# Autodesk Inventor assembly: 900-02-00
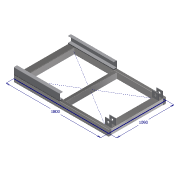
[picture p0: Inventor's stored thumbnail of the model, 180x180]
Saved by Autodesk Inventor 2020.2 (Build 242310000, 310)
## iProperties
Created: 2015-10
Part Number: 900-02-00
Document SubType Name: Konstrukcja spawana
Designer: F.Stasiak
Weld Material: Stal, miękka, spawana
Mass: 81980 g
Surface Area: 59876.8 cm^2
Volume: 13260.1 cm^3
Density: 6.18248 g/cm^3
Catalog Web Link: www.expertbooks.pl
Manager: www.cadconsulting.pl
Company: Fabian Stasiak CAD Consulting
_SolveAssemblyDoc: Frame Generator Solve Assembly
_Version: 15.0.0
Author: F.Stasiak
Subject: Zbiór ćwiczeń. Autodesk Inventor 2020. Kurs Professional
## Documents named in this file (6)
- C:\2020_Kurs_Professional\R3 Dynamika\Komponenty_dyn\900-02-00.iam
- C:\2020_Kurs_Professional\R3 Dynamika\Komponenty_dyn\900-01-00_Szkielet.ipt
- C:\2020_Kurs_Professional\R3 Dynamika\900-01\Frame\Frame_900_01_00.iam
- C:\2020_Kurs_Professional\R3 Dynamika\Komponenty_dyn\900-01-06.ipt
- C:\2020_Kurs_Professional\R3 Dynamika\Komponenty_dyn\900-01-07.ipt
- C:\2020_Kurs_Professional\R3 Dynamika\Komponenty_dyn\EN 10058 - 900-01-08.ipt
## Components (10 placed, 5 different names)
1. 900-01-00_Szkielet:1
2. Frame_900_01_00:1 [sub-assembly] — Zestawiający:1, Równoległy:1, Równoległy:2, Zestawiający:2, Równoległy:3, Równoległy:4, Zestawiający:3, Równoległy:5, Zestawiający:4, Równoległy:7, Równoległy:8, Zestawiający:5, Zestawiający:7, Równoległy:6, Zestawiający:9, Zestawiający:10, Równoległy:13, Równoległy:14, Zestawiający:13
3. 900-01-06:1 — Zestawiający:1, Równoległy:1, Równoległy:2
4. 900-01-06:2 — Zestawiający:2, Równoległy:3, Równoległy:4, Równoległy:11, Równoległy:12
5. 900-01-07:1 — Zestawiający:3, Równoległy:5, Równoległy:6, Równoległy:9, Zestawiający:6
6. 900-01-07:2 — Zestawiający:4, Równoległy:7, Równoległy:8, Równoległy:10, Zestawiający:8
7. 900-01-07:3 — Zestawiający:5, Równoległy:9, Zestawiający:6
8. 900-01-07:4 — Zestawiający:7, Równoległy:10, Zestawiający:8
9. EN 10058 - 900-01-08:1 — Zestawiający:9, Równoległy:11, Równoległy:12
10. EN 10058 - 900-01-08:2 — Zestawiający:10, Równoległy:13, Równoległy:14
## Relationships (25: Flush 14, Mate 11)
- Zestawiający:1 [Mate]: Frame_900_01_00:1 ↔ 900-01-06:1
- Równoległy:1 [Flush]: Frame_900_01_00:1 ↔ 900-01-06:1
- Równoległy:2 [Flush]: Frame_900_01_00:1 ↔ 900-01-06:1
- Zestawiający:2 [Mate]: Frame_900_01_00:1 ↔ 900-01-06:2
- Równoległy:3 [Flush]: Frame_900_01_00:1 ↔ 900-01-06:2
- Równoległy:4 [Flush]: Frame_900_01_00:1 ↔ 900-01-06:2
- Zestawiający:3 [Mate]: Frame_900_01_00:1 ↔ 900-01-07:1
- Równoległy:5 [Flush]: Frame_900_01_00:1 ↔ 900-01-07:1
- Równoległy:6 [Flush]: Frame_900_01_00:1 ↔ 900-01-07:1
- Zestawiający:4 [Mate]: Frame_900_01_00:1 ↔ 900-01-07:2
- Równoległy:7 [Flush]: Frame_900_01_00:1 ↔ 900-01-07:2
- Równoległy:8 [Flush]: Frame_900_01_00:1 ↔ 900-01-07:2
- Zestawiający:5 [Mate]: Frame_900_01_00:1 ↔ 900-01-07:3
- Równoległy:9 [Flush]: 900-01-07:1 ↔ 900-01-07:3
- Zestawiający:6 [Mate]: 900-01-07:1 ↔ 900-01-07:3
- Zestawiający:7 [Mate]: Frame_900_01_00:1 ↔ 900-01-07:4
- Równoległy:10 [Flush]: 900-01-07:2 ↔ 900-01-07:4
- Zestawiający:8 [Mate]: 900-01-07:2 ↔ 900-01-07:4
- Zestawiający:9 [Mate]: Frame_900_01_00:1 ↔ EN 10058 - 900-01-08:1
- Równoległy:11 [Flush]: 900-01-06:2 ↔ EN 10058 - 900-01-08:1
- Równoległy:12 [Flush]: 900-01-06:2 ↔ EN 10058 - 900-01-08:1
- Zestawiający:10 [Mate]: Frame_900_01_00:1 ↔ EN 10058 - 900-01-08:2
- Równoległy:13 [Flush]: Frame_900_01_00:1 ↔ EN 10058 - 900-01-08:2
- Równoległy:14 [Flush]: Frame_900_01_00:1 ↔ EN 10058 - 900-01-08:2
- Zestawiający:13 [Mate]: Frame_900_01_00:1
